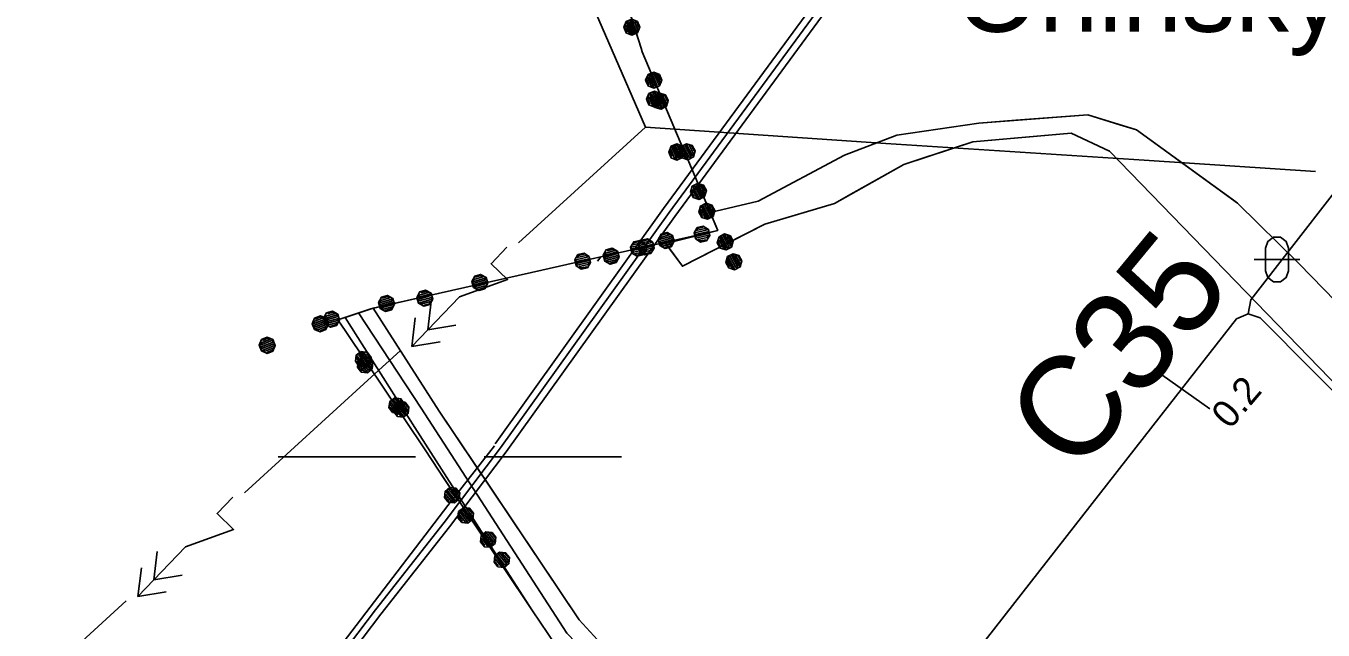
# Model space of a CAD drawing. Extents: x -645676 to -642474, y -1077513 to -1072613.
# Drawn here: x -645443.9 to -645160.5, y -1074894.5 to -1074762.6 of the extents above; entities that cross this region are included whole.
import ezdxf

# ---------------------------------------------------------------- set-up
doc = ezdxf.new("R2010")
doc.units = 0
for name, color, linetype in [('ELEKTRO', 7, 'Continuous'), ('katastr_ln___zem____popis', 7, 'Continuous'), ('KRAJ_ZELEN_STAV', 7, 'Continuous'), ('KULTURY_STAV', 7, 'Continuous'), ('KULTURY_ZNACKY', 7, 'Continuous'), ('NOVY_STAV', 7, 'Continuous'), ('NOVY_STAV_SLATINANY', 7, 'Continuous'), ('OBVOD_PU', 7, 'Continuous'), ('OSA', 7, 'Continuous'), ('PC_NAVRH', 7, 'Continuous'), ('PC_POPIS_NAVRH', 7, 'Continuous'), ('PC_STAN_NAVRH', 7, 'Continuous'), ('SPRAV_HR_STAV', 7, 'Continuous'), ('TRVALY-ZAB-DSP', 7, 'Continuous'), ('Vodn__plocha___st_vaj_c_', 7, 'Continuous'), ('Vodn__tok', 7, 'Continuous')]:
    doc.layers.add(name, color=color, linetype=linetype)

# ---------------------------------------------------------------- blocks, each defined once
blk = doc.blocks.new('$944')
blk.add_line((0, 1.5), (0, -1.5))
blk = doc.blocks.new('8$0300')
for p, q in [((-7.5, 0), (-1.5, 0)), ((1.5, 0), (7.5, 0))]:
    blk.add_line(p, q)
blk = doc.blocks.new('3$1600')
for points in [[(-0.5, 1.5), (-0.4, 1.79), (-0.15, 1.97), (0.16, 1.97), (0.41, 1.79), (0.51, 1.5), (0.51, 0.5), (0.41, 0.21), (0.16, 0.03), (-0.15, 0.03), (-0.4, 0.21), (-0.5, 0.5), (-0.5, 1.5)], [(-1, 1), (0.27, 1), (1, 1)]]:
    blk.add_lwpolyline(points)
blk = doc.blocks.new('6$6120')
for points in [[(-3, 0), (-2, 0), (-2, 1), (0, 0), (3, 0)], [(1, -0.75), (2, 0), (1, 0.75)], [(2, 0.75), (3, 0), (2, -0.75)]]:
    blk.add_lwpolyline(points)
blk = doc.blocks.new('2$0620')
for points in [[(-1.07, 0.32), (-0.88, 0.13), (-0.88, -0.14), (-1.07, -0.33), (-1.34, -0.33), (-1.53, -0.14), (-1.53, 0.13), (-1.34, 0.32), (-1.07, 0.32), (-1.08, 0.28), (-1.32, 0.28), (-1.4, 0.2), (-1, 0.2), (-0.92, 0.12), (-1.48, 0.12), (-1.48, 0.04), (-0.92, 0.04), (-0.92, -0.04), (-1.48, -0.04), (-1.48, -0.12), (-0.92, -0.12), (-1, -0.2), (-1.4, -0.2), (-1.32, -0.28), (-1.08, -0.28)], [(1.43, 0.32), (1.62, 0.13), (1.62, -0.14), (1.43, -0.33), (1.16, -0.33), (0.97, -0.14), (0.97, 0.13), (1.16, 0.32), (1.43, 0.32), (1.4, 0.28), (1.16, 0.28), (1.08, 0.2), (1.48, 0.2), (1.56, 0.12), (1, 0.12), (1, 0.04), (1.56, 0.04), (1.56, -0.04), (1, -0.04), (1, -0.12), (1.56, -0.12), (1.48, -0.2), (1.08, -0.2), (1.16, -0.28), (1.4, -0.28)]]:
    blk.add_lwpolyline(points)

msp = doc.modelspace()

# ---------------------------------------------------------------- linework, layer by layer
at = {"layer": 'ELEKTRO'}
for p, q in [((-645308.55, -1074784.66), (-645326.92, -1074742.28)), ((-645308.55, -1074784.66), (-645336.26, -1074809.93)), ((-645308.55, -1074784.66), (-645256.04, -1074788.23)), ((-645256.04, -1074788.23), (-645199.57, -1074791.89)), ((-645199.57, -1074791.89), (-645162.15, -1074794.37)), ((-645362.12, -1074833.51), (-645368.4, -1074839.23)), ((-645368.4, -1074839.23), (-645396.1, -1074864.5)), ((-645421.96, -1074888.09), (-645443.87, -1074908.08))]:
    msp.add_line(p, q, dxfattribs=at)
at = {"layer": 'KRAJ_ZELEN_STAV'}
for points in [[(-645294.41, -1074803.3), (-645283.91, -1074800.83), (-645265.07, -1074790.79), (-645253.66, -1074786.41), (-645235.7, -1074783.79), (-645211.94, -1074782.03), (-645201.31, -1074785.26), (-645179.19, -1074801.27), (-645165.72, -1074814.56), (-645147.13, -1074833.7)], [(-645152.23, -1074846.64), (-645207.14, -1074789.92), (-645215.56, -1074786.01), (-645237.06, -1074787.87), (-645252.09, -1074792.82), (-645267.21, -1074801.34), (-645282.48, -1074805.84), (-645300.47, -1074815.07), (-645304.11, -1074810.12), (-645292.74, -1074807.25), (-645294.41, -1074803.3)]]:
    msp.add_lwpolyline(points, dxfattribs=at)
at = {"layer": 'KULTURY_STAV'}
for points in [[(-645147.13, -1074833.7), (-645165.72, -1074814.56), (-645179.19, -1074801.27), (-645179.61, -1074800.97), (-645201.31, -1074785.26), (-645204.89, -1074784.17), (-645211.94, -1074782.03), (-645227.62, -1074783.19), (-645235.7, -1074783.79), (-645253.66, -1074786.41), (-645265.07, -1074790.79), (-645283.91, -1074800.83), (-645294.41, -1074803.3), (-645292.74, -1074807.25), (-645299.1, -1074792.24), (-645300.93, -1074787.91), (-645309.27, -1074768.21), (-645309.51, -1074767.46), (-645314.48, -1074751.75)], [(-645152.23, -1074846.64), (-645207.14, -1074789.92), (-645215.56, -1074786.01), (-645225.54, -1074786.87), (-645237.06, -1074787.87), (-645248.14, -1074791.52), (-645252.09, -1074792.82), (-645263, -1074798.97), (-645267.21, -1074801.34), (-645282.49, -1074805.84), (-645287.37, -1074808.34), (-645300.47, -1074815.07), (-645304.31, -1074809.86), (-645292.74, -1074807.25), (-645294.41, -1074803.3), (-645283.91, -1074800.83), (-645265.07, -1074790.79), (-645253.66, -1074786.41), (-645235.7, -1074783.79), (-645227.62, -1074783.19), (-645211.94, -1074782.03)], [(-645211.94, -1074782.03), (-645204.89, -1074784.17), (-645201.31, -1074785.26), (-645179.61, -1074800.97), (-645179.19, -1074801.27), (-645165.72, -1074814.56), (-645147.13, -1074833.7)], [(-645314.19, -1074901.9), (-645323.01, -1074892.28), (-645346.28, -1074857.59), (-645348.51, -1074854.27), (-645353.57, -1074846.73), (-645368.03, -1074824.22), (-645353.81, -1074821.02), (-645333.46, -1074816.43), (-645319.59, -1074813.3), (-645318.3, -1074813.01), (-645292.74, -1074807.25), (-645304.31, -1074809.86), (-645300.47, -1074815.07), (-645287.37, -1074808.34), (-645282.49, -1074805.84), (-645267.21, -1074801.34), (-645263, -1074798.97), (-645252.09, -1074792.82), (-645248.14, -1074791.52), (-645237.06, -1074787.87), (-645225.54, -1074786.87), (-645215.56, -1074786.01), (-645207.14, -1074789.92), (-645152.23, -1074846.64)], [(-645328.21, -1074897.69), (-645333.18, -1074890.27), (-645352.63, -1074861.23), (-645353.73, -1074859.58), (-645356.69, -1074855.16), (-645374, -1074829.29), (-645375.71, -1074826.74), (-645368.56, -1074824.34), (-645368.03, -1074824.22), (-645353.57, -1074846.73), (-645348.51, -1074854.27), (-645346.28, -1074857.59), (-645323.01, -1074892.28), (-645314.19, -1074901.9)]]:
    msp.add_lwpolyline(points, dxfattribs=at)
at = {"layer": 'NOVY_STAV'}
for points in [[(-645341.39, -1074853.82), (-645304.59, -1074802.43), (-645267.14, -1074751.52), (-645238.28, -1074718.59), (-645205.79, -1074692.52), (-645185.43, -1074683.62), (-645169.58, -1074681.8), (-645172.23, -1074674.54), (-645170.18, -1074672.34), (-645163.75, -1074676.83), (-645153.21, -1074682.89), (-645142.08, -1074686.08), (-645138.58, -1074687.23), (-645135.18, -1074688.64), (-645131.9, -1074690.3), (-645091.47, -1074712.73), (-645050.03, -1074732.45), (-644973.68, -1074756.05)], [(-645338.95, -1074855.57), (-645302.15, -1074804.17), (-645264.81, -1074753.42), (-645236.22, -1074720.78), (-645204.21, -1074695.1), (-645184.64, -1074686.55), (-645169.47, -1074684.81), (-645164.45, -1074684.55), (-645159.43, -1074684.93), (-645154.51, -1074685.93), (-645143.42, -1074688.92), (-645139.79, -1074690.06), (-645136.27, -1074691.49), (-645132.87, -1074693.2), (-645092.84, -1074715.4), (-645051.12, -1074735.25), (-644974.57, -1074758.92), (-644816.15, -1074809.18), (-644755.54, -1074831.7), (-644751.49, -1074829.28), (-644747.27, -1074825.06)]]:
    msp.add_lwpolyline(points, dxfattribs=at)
at = {"layer": 'NOVY_STAV_SLATINANY'}
for points in [[(-645377.93, -1074906.3), (-645366.33, -1074890.99), (-645351.36, -1074871.96), (-645338.98, -1074855.6)], [(-645376.69, -1074899.99), (-645351.7, -1074867.27), (-645341.55, -1074854.29)]]:
    msp.add_lwpolyline(points, dxfattribs=at)
at = {"layer": 'OBVOD_PU'}
msp.add_lwpolyline([(-645328.21, -1074897.69), (-645333.18, -1074890.27), (-645353.73, -1074859.58), (-645356.69, -1074855.16), (-645374, -1074829.29), (-645375.71, -1074826.74), (-645368.56, -1074824.34), (-645353.81, -1074821.02), (-645333.46, -1074816.43), (-645319.59, -1074813.3), (-645318.3, -1074813.01), (-645292.74, -1074807.25), (-645299.1, -1074792.24), (-645300.93, -1074787.91), (-645309.27, -1074768.21), (-645309.51, -1074767.46), (-645314.48, -1074751.75)], dxfattribs=at)
at = {"layer": 'OSA'}
msp.add_lwpolyline([(-645379.12, -1074905.39), (-645367.51, -1074890.08), (-645352.54, -1074871.04), (-645340.17, -1074854.69), (-645303.37, -1074803.3), (-645265.98, -1074752.47)], dxfattribs=at)
at = {"layer": 'PC_NAVRH'}
for points in [[(-645176.85, -1074825.42), (-645176.33, -1074822.39), (-645149.12, -1074787.48)], [(-645021.99, -1074891.99), (-645037.6, -1074895.68), (-645059.4, -1074892.54), (-645113.44, -1074873.13), (-645139.31, -1074861.49), (-645174.24, -1074826.29), (-645176.85, -1074825.42), (-645179.43, -1074826.52), (-645194.09, -1074845.22), (-645266.33, -1074937.66)]]:
    msp.add_lwpolyline(points, dxfattribs=at)
at = {"layer": 'SPRAV_HR_STAV'}
for p, q in [((-645314.48, -1074751.75), (-645309.51, -1074767.46)), ((-645309.51, -1074767.46), (-645309.27, -1074768.21)), ((-645309.27, -1074768.21), (-645300.93, -1074787.91)), ((-645300.93, -1074787.91), (-645299.1, -1074792.24)), ((-645299.1, -1074792.24), (-645292.74, -1074807.25)), ((-645292.74, -1074807.25), (-645318.3, -1074813.01)), ((-645333.46, -1074816.43), (-645319.59, -1074813.3)), ((-645319.59, -1074813.3), (-645318.3, -1074813.01)), ((-645333.46, -1074816.43), (-645353.81, -1074821.02)), ((-645353.81, -1074821.02), (-645368.56, -1074824.34)), ((-645368.56, -1074824.34), (-645375.71, -1074826.74)), ((-645375.71, -1074826.74), (-645374, -1074829.29)), ((-645356.69, -1074855.16), (-645374, -1074829.29)), ((-645356.69, -1074855.16), (-645353.73, -1074859.58)), ((-645353.73, -1074859.58), (-645333.18, -1074890.27)), ((-645333.18, -1074890.27), (-645328.21, -1074897.69))]:
    msp.add_line(p, q, dxfattribs=at)
at = {"layer": 'TRVALY-ZAB-DSP'}
for p, q in [((-645318.3, -1074813.01), (-645318.99, -1074813.95)), ((-645375.71, -1074826.74), (-645374, -1074829.29)), ((-645356.69, -1074855.16), (-645374, -1074829.29))]:
    msp.add_line(p, q, dxfattribs=at)
at = {"layer": 'Vodn__plocha___st_vaj_c_'}
for points in [[(-645320.35, -1074905.19), (-645327.69, -1074898.44), (-645328.21, -1074897.69), (-645333.18, -1074890.27), (-645343.74, -1074873.94), (-645358.89, -1074850.26), (-645374.16, -1074826.22), (-645368.02, -1074824.22), (-645353.57, -1074846.73), (-645323.01, -1074892.28), (-645314.19, -1074901.9), (-645269.27, -1074936.11), (-645263.44, -1074940.56), (-645236.45, -1074960.57), (-645186.18, -1074998.83), (-645127.03, -1075043.46), (-645119.22, -1075048.8), (-645115.32, -1075053.06), (-645110.78, -1075056.48), (-645087.88, -1075073.72), (-645037.68, -1075112.27)], [(-645127.03, -1075043.46), (-645186.18, -1074998.83), (-645236.45, -1074960.57), (-645263.44, -1074940.56), (-645269.27, -1074936.11), (-645314.19, -1074901.9), (-645323.01, -1074892.28), (-645353.57, -1074846.73), (-645368.02, -1074824.22), (-645374.16, -1074826.22), (-645358.89, -1074850.26), (-645343.74, -1074873.94), (-645333.18, -1074890.27), (-645328.21, -1074897.69), (-645327.69, -1074898.44), (-645320.35, -1074905.19), (-645272.63, -1074940.93), (-645266.86, -1074945.07), (-645240.04, -1074966.05), (-645189.47, -1075004.6), (-645130.94, -1075048.32)]]:
    msp.add_lwpolyline(points, dxfattribs=at)
at = {"layer": 'Vodn__tok'}
msp.add_lwpolyline([(-644737.28, -1075262.07), (-644790.63, -1075250.71), (-644852.68, -1075237.9), (-644879.87, -1075231.93), (-644887.46, -1075228.4), (-644913.43, -1075209.05), (-644922.62, -1075202.32), (-644931.59, -1075195.91), (-644942.63, -1075187.1), (-644967.94, -1075167.74), (-644997, -1075145.82), (-645040.36, -1075114.96), (-645089.98, -1075076.71), (-645130.46, -1075044.8), (-645189.79, -1075000.02), (-645239.14, -1074962.61), (-645275.37, -1074935.26), (-645317.56, -1074903.59), (-645325.71, -1074895.16), (-645357.55, -1074846.07), (-645371.25, -1074825.24)], dxfattribs=at)

# ---------------------------------------------------------------- block references
at = {"layer": 'ELEKTRO', "yscale": 5}
for p, xscale, rotation in [((-645349.19, -1074821.72), 5, -133.756218), ((-645409.03, -1074876.3), 4.999999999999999, -133.74564100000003)]:
    msp.add_blockref('6$6120', p, dxfattribs=dict(at, xscale=xscale, rotation=rotation))
at = {"layer": 'KULTURY_ZNACKY', "xscale": 5, "yscale": 5}
for name, p in [('3$1600', (-645170.6, -1074818.59)), ('8$0300', (-645351.28, -1074856.69))]:
    msp.add_blockref(name, p, dxfattribs=at)
at = {"layer": 'PC_STAN_NAVRH', "xscale": 5, "yscale": 5, "rotation": -125.06799599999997}
msp.add_blockref('$944', (-645191.37, -1074841.87), dxfattribs=at)
at = {"layer": 'SPRAV_HR_STAV'}
for p, xscale, yscale, rotation in [((-645309.2, -1074768.43), 4.999999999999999, 5, -67.425988), ((-645304.18, -1074784.13), 5, 4.999999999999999, -67.23324000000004), ((-645302.45, -1074784.33), 5, 4.999999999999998, -61.94174600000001), ((-645294.12, -1074804.03), 5, 4.999999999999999, -61.97724299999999), ((-645292.27, -1074808.35), 4.999999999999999, 4.999999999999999, -61.92359399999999), ((-645309.81, -1074811.1), 5, 5, -163.93717700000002), ((-645302.52, -1074809.46), 4.999999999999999, 5, 12.890944), ((-645316.39, -1074812.58), 5.000000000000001, 4.999999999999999, 12.938698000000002), ((-645350.53, -1074820.28), 5, 5.000000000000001, -163.926044), ((-645370.88, -1074824.86), 5, 5, -163.95200700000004), ((-645385.15, -1074829.91), 5, 5.000000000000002, -157.9795), ((-645366.42, -1074840.62), 5, 5, 125.947562), ((-645365.96, -1074841.27), 5.000000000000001, 4.999999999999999, -50.85156200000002), ((-645346.95, -1074869.7), 5, 4.999999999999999, -50.88797699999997), ((-645343.99, -1074874.12), 5, 5, -50.891340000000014)]:
    msp.add_blockref('2$0620', p, dxfattribs=dict(at, xscale=xscale, yscale=yscale, rotation=rotation))

# ---------------------------------------------------------------- texts
at = {"layer": 'katastr_ln___zem____popis'}
msp.add_text('Orlinský', height=17.5, dxfattribs=at).set_placement((-645240.79, -1074763.86))
at = {"layer": 'PC_POPIS_NAVRH'}
msp.add_text('C35', height=22, rotation=50.42, dxfattribs=at).set_placement((-645214.28, -1074861.12))
at = {"layer": 'PC_STAN_NAVRH'}
msp.add_text('0.2', height=6, rotation=49.504, dxfattribs=at).set_placement((-645180.85, -1074850.87))

doc.saveas('drawing.dxf')
